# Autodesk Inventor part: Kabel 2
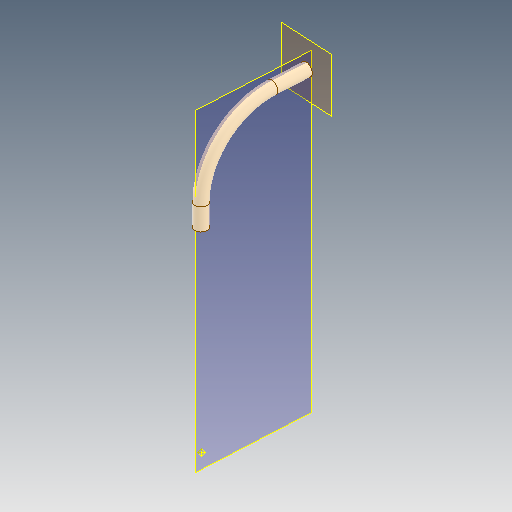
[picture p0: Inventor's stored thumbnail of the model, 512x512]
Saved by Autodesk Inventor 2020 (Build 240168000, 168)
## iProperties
Created: 2025-04
Part Number: Kabel 2
Material: Polyetylen, S vysokou hustotou
Document SubType Name: Modeling
Designer: doma
Density: 0.952 g/cm^3
Appearance: Hladká – špinavě bílá
Mass: 1.23488 g
Surface Area: 10.7699 cm^2
Volume: 1.29715 cm^3
Author: doma
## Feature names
1. Tažení1
## Parameters: d0 = 5 mm, d1 = 0, d2 = 0
